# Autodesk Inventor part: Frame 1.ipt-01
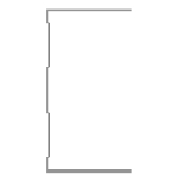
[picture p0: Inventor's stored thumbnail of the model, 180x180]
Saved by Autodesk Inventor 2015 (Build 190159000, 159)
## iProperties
IsCustomPart: 1
Created: 2015-04
Part Number: Frame 1.ipt-01
Material: Aluminum 6061
Description: Kévin Novo
Document SubType Name: Modeling
Standard: Kevin
Designer: suporte
Standards Organization: Kevin
Language: en-US
Size Designation: (Unnamed 1)
Categories: <MemberInstance><Categories><Category DisplayName="Structural Shapes" InternalName="089c4875-fa83-4c05-b084-43b9cc11f5ed" Mnemonic="GRDR"><CategoryParameter Dis
Density: 2.7 g/cm^3
Appearance: Aluminum - Flat
G_L: 1275,000 mm
G_W: 50,000 mm
G_H: 75,000 mm
+D87C0F32-8461-4F19-A6E5-F7FFCE7659D3+CUTDETAIL1: Cut
+ACB6C8C3-AA69-4D4C-B27A-0D4BF8BA8BC6+CUTDETAIL2: Cut
_CCFamilyMember: 1
_CCFamilyDisplayName: Kévin - Kévin Novo
_FrameMemberDoc: Frame Member File
_Version: 15.0.0
_GetPNFromCC: 1
Author: suporte
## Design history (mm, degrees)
node "Start Plane"
node "End Plane"
sketch "Sketch"
  geometry: L1 (24.7, 37.5)-(24.7, 36.9); L2 (24.7, 36.9)-(-24.7, 36.9); L3 (-24.7, -36.9)-(24.7, -36.9); L4 (24.7, -36.9)-(24.7, -37.5); L5 (24.7, -37.5)-(-25.3, -37.5); L6 (-25.3, 37.5)-(24.7, 37.5); L7 (-24.7, 36.9)-(-24.7, 31.9); L8 (-24.7, 31.9)-(-23.3, 30.5); L9 (-23.3, 30.5)-(-23.3, 10.934); L10 (-23.3, 10.934)-(-24.7, 9.534); L11 (-24.7, 9.534)-(-24.7, -9.534); L12 (-24.7, -9.534)-(-23.3, -10.934); L13 (-23.3, -10.934)-(-23.3, -30.5); L14 (-23.3, -30.5)-(-24.7, -31.9); L15 (-24.7, -31.9)-(-24.7, -36.9); L16 (-25.3, -37.5)-(-25.3, -31.651); L17 (-25.3, -31.651)-(-23.9, -30.251); L18 (-23.9, -30.251)-(-23.9, -11.183); L19 (-23.9, -11.183)-(-25.3, -9.783); L20 (-25.3, -9.783)-(-25.3, 9.783); L21 (-25.3, 9.783)-(-23.9, 11.183); L22 (-23.9, 11.183)-(-23.9, 30.251); L23 (-23.9, 30.251)-(-25.3, 31.651); L24 (-25.3, 31.651)-(-25.3, 37.5); L25 (-25.3, 0)-(30.37, 0); 3 further points
  constraints: 50 end point, 10 point on line, 9 parallel, 5 perpendicular, 4 equal length, 3 midpoint, 3 vertical, 2 vertical alignment, 1 collinear, 1 horizontal, 1 horizontal alignment
  dimensions: "d3" = 0.6 distance of L1.start L1.end (= d6); "d5" = 75 distance between parallel lines of L5 L6; "d6" = 0.6 distance between parallel lines of L24 L7 (= d8); "d7" = 0.6 distance between parallel lines of L8 L23 (= d8); "d8" = 0.6 distance between parallel lines of L22 L9 (= d12); "Espessura" = 0.6 distance between parallel lines of L17 L14; "d10" = 0.6 distance between parallel lines of L13 L18 (= Espessura); "d11" = 0.6 distance between parallel lines of L12 L19 (= Espessura); "d12" = 0.6 distance between parallel lines of L21 L10 (= d11); "d13" = 5 distance of L2.end L7.end; "d15" = 135 deg angle of L9 L8; "d16" = 2 distance between parallel lines of L24 L9; "d17" = 50 distance of L6.start L1.start
extrude "Body" join sketch "Sketch" stored distance "d24" = 0.13; taper "d25" = 0 deg
node "Driven Length"
  sketch "Sketch10"
    geometry: L1 (0, 0)-(10, 0) reference
    constraints: 2 end point, 1 horizontal
  workplane "Work Plane7"
  sketch "Sketch11"
    geometry: L1 (-2, 12.5)-(12, 12.5) reference; L2 (-2, 1287.5)-(12, 1287.5) reference
    dimensions: "d27" = 1275 distance between parallel lines of L1 L2 (derived)
workplane "Work Plane8"
split "Split1"
workplane "Work Plane9"
split "Split2"
body "Solid1"
other parameters: "G_OFFSET_START" = -12.5 [user parameter; used in 1 equation term], "G_OFFSET_END" = 87.5 [user parameter; used in 1 equation term], "d22" = 12.5 (= -G_OFFSET_START), "d23" = 1287.5 (= tamanho + G_OFFSET_END), "G_L" = 1275 (= d27) [user parameter], "d34" = 90 deg
